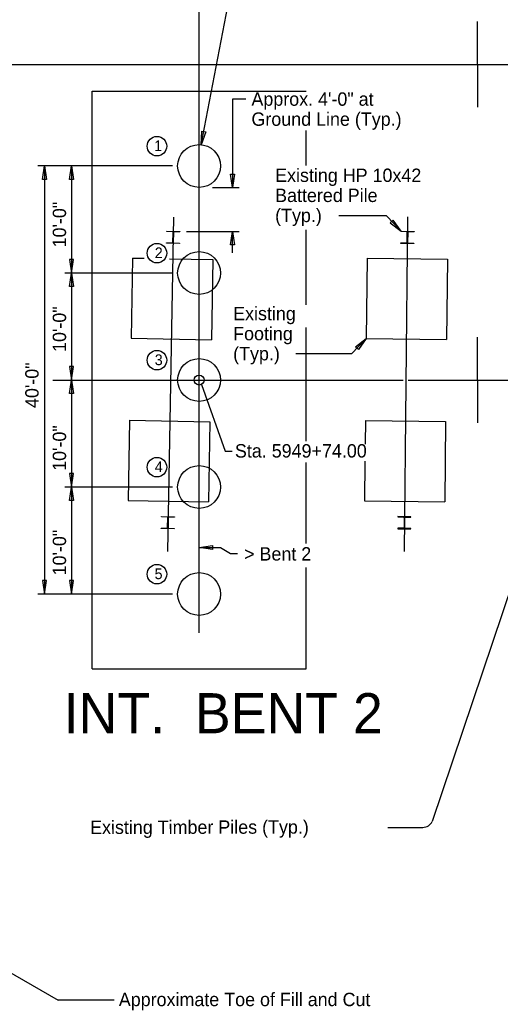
# Model space of a CAD drawing. Extents: x -10371 to -10009, y 1939 to 2167.
# Drawn here: x -10303.7 to -10258.8, y 2025.6 to 2118.2 of the extents above; entities that cross this region are included whole.
import ezdxf

# ---------------------------------------------------------------- set-up
doc = ezdxf.new("R2010")
doc.units = 0
for name, color, linetype in [('BR_AUTO DIMENSION', 7, 'Continuous'), ('BR_CENTER LINES', 7, 'Continuous'), ('BR_CONCRETE', 7, 'Continuous'), ('BR_STRUCTURAL STEEL', 7, 'Continuous'), ('BR_TABLE LINES', 7, 'Continuous'), ('BR_TEXT', 7, 'Continuous')]:
    doc.layers.add(name, color=color, linetype=linetype)

msp = doc.modelspace()

# ---------------------------------------------------------------- linework, layer by layer
at = {"layer": 'BR_AUTO DIMENSION'}
for p, q in [((-10286.716, 2106.484), (-10283.789, 2121.639)), ((-10282.559, 2110.73), (-10283.789, 2110.73)), ((-10283.789, 2110.73), (-10283.789, 2102.494)), ((-10289.396, 2104.494), (-10301.966, 2104.494)), ((-10301.341, 2104.494), (-10301.341, 2064.494)), ((-10298.841, 2104.494), (-10298.841, 2104.494)), ((-10298.841, 2104.494), (-10298.841, 2064.494)), ((-10285.662, 2102.494), (-10283.164, 2102.494)), ((-10269.411, 2099.836), (-10273.861, 2099.836)), ((-10268.046, 2098.4), (-10269.411, 2099.836)), ((-10288.091, 2098.381), (-10283.164, 2098.381)), ((-10283.789, 2096.381), (-10283.789, 2098.381)), ((-10289.396, 2094.494), (-10299.466, 2094.494)), ((-10271.296, 2088.367), (-10272.661, 2086.931)), ((-10272.661, 2086.931), (-10277.881, 2086.931)), ((-10286.699, 2084.074), (-10284.477, 2077.832)), ((-10284.477, 2077.832), (-10283.824, 2077.832)), ((-10289.396, 2074.494), (-10299.466, 2074.494)), ((-10254.887, 2073.721), (-10265.123, 2043.236)), ((-10286.912, 2068.833), (-10284.908, 2068.833)), ((-10284.908, 2068.833), (-10283.969, 2068.293)), ((-10283.969, 2068.293), (-10283.319, 2068.293)), ((-10289.396, 2064.494), (-10301.966, 2064.494)), ((-10298.841, 2064.494), (-10298.841, 2064.494)), ((-10269.277, 2042.689), (-10266.014, 2042.689)), ((-10307.928, 2031.036), (-10300.079, 2026.551)), ((-10294.829, 2026.551), (-10300.079, 2026.551))]:
    msp.add_line(p, q, dxfattribs=at)
for points in [[(-10286.292, 2107.675), (-10286.715, 2106.484), (-10286.66, 2107.747)], [(-10301.528, 2103.244), (-10301.341, 2104.494), (-10301.153, 2103.244)], [(-10299.028, 2103.244), (-10298.841, 2104.494), (-10298.653, 2103.244)], [(-10283.601, 2103.744), (-10283.789, 2102.494), (-10283.976, 2103.744)], [(-10269.05, 2099.169), (-10268.046, 2098.4), (-10268.78, 2099.429)], [(-10283.976, 2097.131), (-10283.789, 2098.381), (-10283.601, 2097.131)], [(-10299.028, 2095.744), (-10298.841, 2094.494), (-10298.653, 2095.744)], [(-10299.028, 2093.244), (-10298.841, 2094.494), (-10298.653, 2093.244)], [(-10272.299, 2087.598), (-10271.296, 2088.367), (-10272.03, 2087.338)], [(-10299.028, 2085.744), (-10298.841, 2084.494), (-10298.653, 2085.744)], [(-10299.028, 2083.244), (-10298.841, 2084.494), (-10298.653, 2083.244)], [(-10299.028, 2075.744), (-10298.841, 2074.494), (-10298.653, 2075.744)], [(-10299.028, 2073.244), (-10298.841, 2074.494), (-10298.653, 2073.244)], [(-10285.662, 2068.646), (-10286.912, 2068.833), (-10285.662, 2069.021)], [(-10301.528, 2065.744), (-10301.341, 2064.494), (-10301.153, 2065.744)], [(-10299.028, 2065.744), (-10298.841, 2064.494), (-10298.653, 2065.744)]]:
    msp.add_lwpolyline(points, close=True, dxfattribs=at)
msp.add_circle((-10286.909, 2084.493), 0.469, dxfattribs=at)
msp.add_arc((-10266.014, 2043.689), 1, 270, 333.07749, dxfattribs=at)
at = {"layer": 'BR_CENTER LINES'}
for p, q in [((-10286.912, 2060.869), (-10286.912, 2124.664)), ((-10260.91, 2113.994), (-10260.91, 2117.994)), ((-10352.245, 2113.994), (-10015.579, 2113.994)), ((-10260.91, 2113.994), (-10260.91, 2109.994)), ((-10267.425, 2099.73), (-10267.758, 2068.475)), ((-10260.913, 2084.494), (-10260.913, 2088.494)), ((-10300.563, 2084.494), (-10267.859, 2084.494)), ((-10267.366, 2084.494), (-10256.576, 2084.494)), ((-10260.913, 2084.494), (-10260.913, 2080.494))]:
    msp.add_line(p, q, dxfattribs=at)
at = {"layer": 'BR_CONCRETE'}
for p, q in [((-10293.12, 2095.894), (-10293.257, 2088.395)), ((-10293.12, 2095.894), (-10292.041, 2095.874)), ((-10289.683, 2095.831), (-10285.621, 2095.756)), ((-10285.621, 2095.756), (-10285.758, 2088.258)), ((-10271.216, 2095.866), (-10271.296, 2088.367)), ((-10271.216, 2095.866), (-10263.716, 2095.786)), ((-10263.716, 2095.786), (-10263.796, 2088.287)), ((-10293.257, 2088.395), (-10285.758, 2088.258)), ((-10271.296, 2088.367), (-10263.796, 2088.287)), ((-10293.397, 2080.73), (-10293.535, 2073.231)), ((-10293.397, 2080.73), (-10285.898, 2080.592)), ((-10285.898, 2080.592), (-10286.036, 2073.094)), ((-10271.378, 2080.701), (-10271.401, 2078.499)), ((-10271.378, 2080.701), (-10263.878, 2080.621)), ((-10263.878, 2080.621), (-10263.958, 2073.121)), ((-10271.418, 2076.903), (-10271.458, 2073.201)), ((-10293.535, 2073.231), (-10286.036, 2073.094)), ((-10271.458, 2073.201), (-10263.958, 2073.121))]:
    msp.add_line(p, q, dxfattribs=at)
for centre in [(-10286.912, 2104.494), (-10286.912, 2094.494), (-10286.912, 2084.494), (-10286.912, 2074.494), (-10286.912, 2064.494)]:
    msp.add_circle(centre, 2, dxfattribs=at)
at = {"layer": 'BR_STRUCTURAL STEEL'}
for p, q in [((-10289.932, 2098.361), (-10289.931, 2098.403)), ((-10289.402, 2098.351), (-10289.932, 2098.361)), ((-10289.931, 2098.403), (-10288.716, 2098.381)), ((-10289.363, 2097.357), (-10289.346, 2098.293)), ((-10289.304, 2098.292), (-10289.321, 2097.356)), ((-10288.716, 2098.339), (-10289.246, 2098.348)), ((-10288.716, 2098.381), (-10288.716, 2098.339)), ((-10268.047, 2098.358), (-10268.046, 2098.4)), ((-10267.517, 2098.352), (-10268.047, 2098.358)), ((-10268.046, 2098.4), (-10266.831, 2098.387)), ((-10267.471, 2097.358), (-10267.461, 2098.295)), ((-10267.419, 2098.294), (-10267.429, 2097.358)), ((-10266.832, 2098.345), (-10267.361, 2098.35)), ((-10266.831, 2098.387), (-10266.832, 2098.345)), ((-10289.952, 2097.269), (-10289.951, 2097.311)), ((-10288.736, 2097.247), (-10289.952, 2097.269)), ((-10289.951, 2097.311), (-10289.421, 2097.301)), ((-10289.265, 2097.298), (-10288.736, 2097.289)), ((-10288.736, 2097.289), (-10288.736, 2097.247)), ((-10268.059, 2097.266), (-10268.058, 2097.308)), ((-10266.843, 2097.253), (-10268.059, 2097.266)), ((-10268.058, 2097.308), (-10267.528, 2097.302)), ((-10267.373, 2097.3), (-10266.843, 2097.295)), ((-10266.843, 2097.295), (-10266.843, 2097.253)), ((-10290.42, 2071.699), (-10290.419, 2071.741)), ((-10289.89, 2071.689), (-10290.42, 2071.699)), ((-10290.419, 2071.741), (-10289.204, 2071.718)), ((-10289.851, 2070.695), (-10289.834, 2071.631)), ((-10289.792, 2071.63), (-10289.809, 2070.694)), ((-10289.205, 2071.676), (-10289.734, 2071.686)), ((-10289.204, 2071.718), (-10289.205, 2071.676)), ((-10268.331, 2071.735), (-10268.332, 2071.693)), ((-10268.332, 2071.693), (-10267.802, 2071.687)), ((-10267.116, 2071.722), (-10268.331, 2071.735)), ((-10267.746, 2071.629), (-10267.756, 2070.693)), ((-10267.713, 2070.693), (-10267.703, 2071.629)), ((-10267.646, 2071.685), (-10267.116, 2071.68)), ((-10267.116, 2071.68), (-10267.116, 2071.722)), ((-10290.44, 2070.607), (-10290.439, 2070.649)), ((-10289.225, 2070.584), (-10290.44, 2070.607)), ((-10290.439, 2070.649), (-10289.909, 2070.639)), ((-10289.753, 2070.636), (-10289.224, 2070.627)), ((-10289.224, 2070.627), (-10289.225, 2070.584)), ((-10267.813, 2070.637), (-10268.343, 2070.643)), ((-10268.343, 2070.643), (-10268.343, 2070.601)), ((-10268.343, 2070.601), (-10267.128, 2070.588)), ((-10267.127, 2070.63), (-10267.657, 2070.635)), ((-10267.128, 2070.588), (-10267.127, 2070.63))]:
    msp.add_line(p, q, dxfattribs=at)
for centre, start, end in [((-10289.403, 2098.294), 358.951, 88.951), ((-10289.247, 2098.291), 88.951, 178.951), ((-10267.518, 2098.295), 359.3884, 89.3884), ((-10267.362, 2098.294), 89.3884, 179.3884), ((-10289.42, 2097.358), 268.951, 358.951), ((-10289.264, 2097.355), 178.951, 268.951), ((-10267.528, 2097.359), 269.3884, 359.3884), ((-10267.372, 2097.357), 179.3884, 269.3884), ((-10289.891, 2071.632), 358.951, 88.951), ((-10289.735, 2071.629), 88.951, 178.951), ((-10267.802, 2071.63), 359.3884, 89.3884), ((-10267.647, 2071.628), 89.3884, 179.3884), ((-10289.908, 2070.696), 268.951, 358.951), ((-10289.752, 2070.693), 178.951, 268.951), ((-10267.812, 2070.694), 269.3884, 359.3884), ((-10267.657, 2070.692), 179.3884, 269.3884)]:
    msp.add_arc(centre, 0.0569, start, end, dxfattribs=at)
at = {"layer": 'BR_TABLE LINES'}
for p, q in [((-10296.912, 2111.494), (-10276.912, 2111.494)), ((-10296.912, 2057.494), (-10296.912, 2111.494)), ((-10276.912, 2104.53), (-10276.912, 2107.803)), ((-10289.299, 2099.714), (-10289.871, 2068.459)), ((-10267.425, 2099.73), (-10267.758, 2068.475)), ((-10276.912, 2091.527), (-10276.912, 2098.533)), ((-10276.912, 2078.792), (-10276.912, 2089.39)), ((-10276.912, 2069.221), (-10276.912, 2076.784)), ((-10276.912, 2057.494), (-10276.912, 2066.981)), ((-10296.912, 2057.494), (-10276.912, 2057.494)), ((-10296.912, 2057.494), (-10276.912, 2057.494))]:
    msp.add_line(p, q, dxfattribs=at)
at = {"layer": 'BR_TEXT'}
for centre in [(-10290.847, 2106.348), (-10290.847, 2096.348), (-10290.847, 2086.348), (-10290.847, 2076.348), (-10290.847, 2066.348)]:
    msp.add_circle(centre, 0.91, dxfattribs=at)

# ---------------------------------------------------------------- texts
at = {"layer": 'BR_AUTO DIMENSION'}
for s, p in [('Approx. 4\'-0" at', (-10282.02, 2110.124)), ('Ground Line (Typ.)', (-10282.02, 2108.249)), ('Existing HP 10x42 ', (-10279.808, 2103.002)), ('Battered Pile ', (-10279.808, 2101.127)), ('(Typ.)', (-10279.808, 2099.252)), ('Existing ', (-10283.729, 2090.08)), ('Footing', (-10283.729, 2088.205)), ('(Typ.)', (-10283.729, 2086.33))]:
    msp.add_text(s, height=1.25, dxfattribs=at).set_placement(p)
at = {"layer": 'BR_TEXT'}
for s, height, p in [('1', 1, (-10291.11, 2105.882)), ('2', 1, (-10291.054, 2095.882)), ('3', 1, (-10291.054, 2085.882)), ('Sta. 5949+74.00', 1.25, (-10283.562, 2077.249)), ('4', 1, (-10291.054, 2075.882)), ('> Bent 2', 1.25, (-10282.706, 2067.621)), ('5', 1, (-10291.068, 2065.882)), ('Approximate Toe of Fill and Cut', 1.25, (-10294.411, 2025.98))]:
    msp.add_text(s, height=height, dxfattribs=at).set_placement(p)
for s, height, rotation, p in [('10\'-0"', 1.25, 90, (-10299.337, 2096.887)), ('10\'-0"', 1.25, 90, (-10299.337, 2087.117)), ('40\'-0"', 1.25, 90, (-10301.901, 2081.878)), ('10\'-0"', 1.25, 90, (-10299.337, 2076.004)), ('10\'-0"', 1.25, 90, (-10299.337, 2066.235)), ('INT.  BENT 2', 3.75, 360, (-10299.559, 2051.48)), ('Existing Timber Piles (Typ.)', 1.25, 0.10672, (-10297.093, 2042.065))]:
    msp.add_text(s, height=height, rotation=rotation, dxfattribs=at).set_placement(p)

doc.saveas('drawing.dxf')
